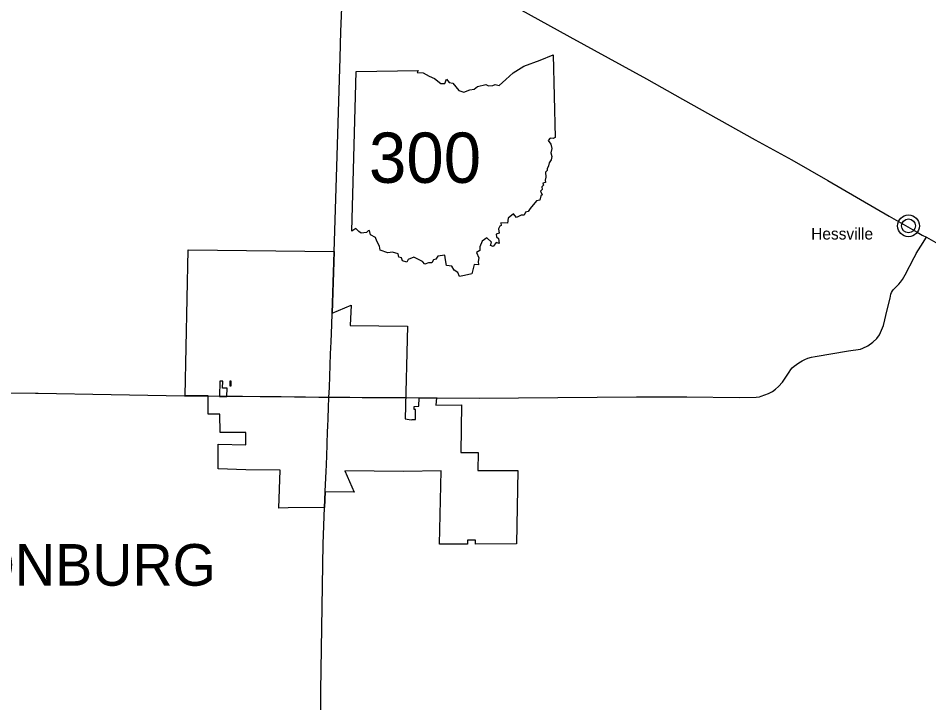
# Model space of a CAD drawing. Extents: x 0 to 798, y 0 to 440.
# Drawn here: x 204.7 to 286.7, y 218.5 to 280.2 of the extents above; entities that cross this region are included whole.
import ezdxf

# ---------------------------------------------------------------- set-up
doc = ezdxf.new("R2010")
doc.units = 0
for name, color, linetype in [('DV_X_Corp_Line', 7, 'Continuous'), ('GM_X_Corporation_Text', 7, 'Continuous'), ('GM_X_State_Route', 7, 'Continuous'), ('GM_X_US_Route', 7, 'Continuous'), ('PV_P_Text', 7, 'Continuous')]:
    doc.layers.add(name, color=color, linetype=linetype)

msp = doc.modelspace()

# ---------------------------------------------------------------- linework, layer by layer
at = {"layer": 'DV_X_Corp_Line'}
for points in [[(219.728, 246.15), (219.998, 259.294), (233.156, 259.134), (232.97, 253.586), (234.689, 254.313), (234.595, 252.489), (239.757, 252.419), (239.527, 244.072), (240.081, 243.994), (240.156, 244.005), (240.473, 244.016), (240.473, 244.919), (240.355, 244.915), (240.36, 245.19), (240.773, 245.205), (240.786, 245.983), (242.357, 245.974), (242.31, 245.31), (244.605, 245.35), (244.559, 241.044), (246.125, 241.04), (246.097, 239.439), (249.689, 239.424), (249.575, 232.818), (245.879, 232.806), (245.884, 233.144), (245.155, 233.144), (245.158, 232.795), (242.623, 232.78), (242.792, 239.381), (239.397, 239.345), (234.094, 239.401), (234.954, 237.463), (232.34, 237.513), (232.29, 236.107), (232.215, 236.105), (228.993, 236.049), (228.169, 236.035), (228.288, 239.462), (225.178, 239.495), (222.704, 239.578), (222.703, 241.784), (225.178, 241.728), (225.177, 242.849), (222.866, 242.849), (222.865, 244.5), (221.792, 244.499), (221.792, 246.15)], [(222.835, 246.103), (223.495, 246.103), (223.51, 246.832), (223.097, 246.841), (223.11, 247.466), (222.862, 247.471)], [(223.763, 247.466), (223.763, 247.036), (223.886, 247.036), (223.886, 247.466)]]:
    msp.add_lwpolyline(points, close=True, dxfattribs=at)
for radius in [0.982, 0.623]:
    msp.add_circle((284.866, 261.455), radius, dxfattribs=at)
at = {"layer": 'GM_X_State_Route'}
for points in [[(233.688, 276.598), (233.761, 278.953), (234.187, 289.718)], [(233.151, 259.127), (233.151, 259.127), (233.357, 265.82), (233.688, 276.598)], [(242.409, 245.974), (246.275, 245.95), (249.739, 245.974), (260.368, 246.047), (264.899, 246.045), (269.615, 246.01), (271.148, 246.023), (271.437, 246.057), (271.608, 246.111), (272.268, 246.35), (272.618, 246.552), (272.889, 246.744), (273.169, 246.993), (273.523, 247.391), (273.698, 247.653), (274.129, 248.295), (274.256, 248.525), (274.392, 248.66), (274.572, 248.82), (274.771, 248.976), (274.988, 249.125), (275.3, 249.304), (275.529, 249.417), (275.798, 249.528), (276.123, 249.629), (276.449, 249.704), (279.451, 250.21), (280.531, 250.366), (280.767, 250.436), (281.19, 250.639), (281.65, 250.994), (282.017, 251.314), (282.244, 251.634), (282.626, 252.497), (282.945, 253.887), (283.205, 254.948), (283.285, 255.318), (283.347, 255.467), (283.434, 255.602), (283.53, 255.721), (284.002, 256.196), (284.14, 256.375), (284.318, 256.624), (284.569, 257.037), (285.386, 258.607), (285.489, 258.816), (285.561, 258.97), (285.981, 259.627), (286.497, 260.433)], [(232.97, 253.586), (233.151, 259.127)], [(232.929, 252.544), (232.97, 253.586)], [(232.693, 246.423), (232.713, 246.941), (232.749, 247.881), (232.789, 248.92), (232.829, 249.943), (232.87, 251.006), (232.929, 252.535), (232.929, 252.544), (232.929, 252.544)], [(154.847, 246.999), (179.742, 246.677), (193.009, 246.54), (193.045, 246.503), (206.237, 246.386), (206.237, 246.386)], [(206.237, 246.386), (206.501, 246.383), (213.058, 246.26), (219.666, 246.156)], [(219.666, 246.156), (222.874, 246.131), (222.951, 246.131)], [(222.951, 246.131), (222.954, 246.131), (223.608, 246.125)], [(223.608, 246.125), (223.611, 246.125), (223.887, 246.123), (224.003, 246.122)], [(224.003, 246.122), (224.006, 246.122), (224.906, 246.115), (226.496, 246.103), (227.556, 246.094), (228.331, 246.085), (228.387, 246.084), (229.585, 246.07), (230.573, 246.058)], [(230.573, 246.058), (231.762, 246.043), (232.677, 246.032), (233.211, 246.029), (233.211, 246.029)], [(232.629, 244.985), (232.633, 245.067), (232.677, 246.032), (232.693, 246.423)], [(233.211, 246.029), (233.628, 246.026), (234.546, 246.021), (235.669, 246.014), (236.503, 246.009), (237.395, 246.004), (238.298, 245.998), (239.2, 245.993), (239.61, 245.99)], [(239.61, 245.99), (240.809, 245.983)], [(240.809, 245.983), (242.409, 245.974)], [(232.594, 244.199), (232.594, 244.209), (232.595, 244.239), (232.629, 244.985)], [(232.561, 243.021), (232.569, 243.306), (232.594, 244.199)], [(232.426, 239.354), (232.449, 239.911), (232.524, 241.693), (232.561, 243.018), (232.561, 243.021)], [(232.35, 237.522), (232.426, 239.351), (232.426, 239.354)], [(232.289, 236.082), (232.349, 237.519), (232.35, 237.522)], [(231.906, 206.373), (231.936, 219.585), (232.153, 232.809), (232.289, 236.082)]]:
    msp.add_lwpolyline(points, dxfattribs=at)
at = {"layer": 'GM_X_US_Route'}
for points in [[(248.019, 282.038), (254.368, 278.485), (261.264, 274.686), (264.516, 272.877), (271.054, 269.205), (274.346, 267.401), (277.607, 265.533), (283.14, 262.329), (283.955, 261.858), (284.816, 261.359), (285.651, 260.876), (285.787, 260.797)], [(285.787, 260.797), (286.094, 260.619), (286.497, 260.433)], [(286.497, 260.433), (287.526, 259.845)]]:
    msp.add_lwpolyline(points, dxfattribs=at)
at = {"layer": 'PV_P_Text'}
msp.add_line((234.737, 260.995), (235.139, 275.358), dxfattribs=at)
msp.add_line((234.737, 260.995), (235.139, 275.358), dxfattribs=at)
for points in [[(235.139, 275.358), (240.711, 275.451), (240.624, 275.278), (241.15, 275.241), (241.709, 274.934), (242.181, 274.741), (242.759, 274.284), (243.105, 274.289), (243.251, 274.664), (243.516, 274.375), (243.83, 274.323), (244.373, 273.636), (244.822, 273.487), (245.359, 273.722), (245.76, 273.761), (246.053, 273.994), (246.818, 274.193), (247.032, 274.074), (247.436, 274.098), (247.64, 274.186), (247.993, 274.107), (248.615, 274.629), (249.255, 275.245), (250.239, 275.826), (251.709, 276.377), (252.871, 276.869), (253.039, 269.415)], [(235.139, 275.358), (240.711, 275.451), (240.624, 275.278), (241.15, 275.241), (241.709, 274.934), (242.181, 274.741), (242.759, 274.284), (243.105, 274.289), (243.251, 274.664), (243.516, 274.375), (243.83, 274.323), (244.373, 273.636), (244.822, 273.487), (245.359, 273.722), (245.76, 273.761), (246.053, 273.994), (246.818, 274.193), (247.032, 274.074), (247.436, 274.098), (247.64, 274.186), (247.993, 274.107), (248.615, 274.629), (249.255, 275.245), (250.239, 275.826), (251.709, 276.377), (252.871, 276.869), (253.039, 269.415)], [(253.039, 269.415), (252.868, 269.311), (252.601, 269.36), (252.421, 269.151), (252.643, 268.802), (252.748, 268.434), (252.655, 268.028), (252.747, 267.693), (252.685, 267.412), (252.517, 267.133), (252.459, 266.867), (252.316, 266.587), (252.328, 266.43), (252.192, 266.306), (252.217, 265.84), (252.148, 265.581), (252.171, 265.359), (251.951, 265.3), (252.001, 265.116), (251.861, 264.974), (251.891, 264.729), (251.732, 264.573), (251.886, 264.26), (251.762, 264.161), (251.659, 263.781), (251.376, 263.704), (250.81, 263.008), (250.61, 262.745), (250.385, 262.68), (250.261, 262.41), (249.985, 262.408), (249.566, 262.221), (249.295, 262.544), (248.821, 262.156), (248.767, 261.708), (248.167, 261.722), (248.19, 261.496), (248.057, 261.43), (247.935, 261.203), (248.006, 260.8), (247.725, 260.697), (247.759, 260.463), (247.939, 260.32), (248.019, 259.873), (247.72, 259.963), (247.476, 259.587), (247.225, 259.675), (247.307, 259.994), (246.883, 260.378), (246.481, 260.071), (246.271, 259.579), (246.269, 259.249), (245.97, 259.049), (246.162, 258.582), (246.127, 258.26), (246.132, 257.955), (245.758, 257.965), (245.532, 257.141)], [(253.039, 269.415), (252.868, 269.311), (252.601, 269.36), (252.421, 269.151), (252.643, 268.802), (252.748, 268.434), (252.655, 268.028), (252.747, 267.693), (252.685, 267.412), (252.517, 267.133), (252.459, 266.867), (252.316, 266.587), (252.328, 266.43), (252.192, 266.306), (252.217, 265.84), (252.148, 265.581), (252.171, 265.359), (251.951, 265.3), (252.001, 265.116), (251.861, 264.974), (251.891, 264.729), (251.732, 264.573), (251.886, 264.26), (251.762, 264.161), (251.659, 263.781), (251.376, 263.704), (250.81, 263.008), (250.61, 262.745), (250.385, 262.68), (250.261, 262.41), (249.985, 262.408), (249.566, 262.221), (249.295, 262.544), (248.821, 262.156), (248.767, 261.708), (248.167, 261.722), (248.19, 261.496), (248.057, 261.43), (247.935, 261.203), (248.006, 260.8), (247.725, 260.697), (247.759, 260.463), (247.939, 260.32), (248.019, 259.873), (247.72, 259.963), (247.476, 259.587), (247.225, 259.675), (247.307, 259.994), (246.883, 260.378), (246.481, 260.071), (246.271, 259.579), (246.269, 259.249), (245.97, 259.049), (246.162, 258.582), (246.127, 258.26), (246.132, 257.955), (245.758, 257.965), (245.532, 257.141)], [(245.532, 257.141), (244.881, 256.983), (244.43, 256.889), (244.271, 257.263), (243.948, 257.461), (243.738, 257.838), (243.274, 257.889), (243.164, 258.407), (243.113, 258.827), (242.479, 258.724), (242.305, 258.467), (242.08, 258.398), (241.949, 258.139), (241.643, 258.117), (241.314, 257.995), (241.099, 258.249), (240.56, 258.504), (240.318, 258.636), (239.812, 258.431), (239.704, 258.189), (239.3, 258.296), (239.206, 258.566), (238.962, 258.647), (238.908, 258.933), (238.387, 259.085), (237.988, 259.025), (237.284, 259.255), (237.242, 259.631), (237.002, 260.09), (236.877, 260.408), (236.432, 260.651), (236.342, 261.03), (236.2, 261.019), (236.07, 260.865), (235.576, 260.795), (235.379, 260.949), (235.102, 261.213), (234.737, 260.995)], [(245.532, 257.141), (244.881, 256.983), (244.43, 256.889), (244.271, 257.263), (243.948, 257.461), (243.738, 257.838), (243.274, 257.889), (243.164, 258.407), (243.113, 258.827), (242.479, 258.724), (242.305, 258.467), (242.08, 258.398), (241.949, 258.139), (241.643, 258.117), (241.314, 257.995), (241.099, 258.249), (240.56, 258.504), (240.318, 258.636), (239.812, 258.431), (239.704, 258.189), (239.3, 258.296), (239.206, 258.566), (238.962, 258.647), (238.908, 258.933), (238.387, 259.085), (237.988, 259.025), (237.284, 259.255), (237.242, 259.631), (237.002, 260.09), (236.877, 260.408), (236.432, 260.651), (236.342, 261.03), (236.2, 261.019), (236.07, 260.865), (235.576, 260.795), (235.379, 260.949), (235.102, 261.213), (234.737, 260.995)]]:
    msp.add_lwpolyline(points, dxfattribs=at)

# ---------------------------------------------------------------- texts
at = {"layer": 'DV_X_Corp_Line'}
msp.add_text('Hessville', height=1.0417, rotation=0.00001, dxfattribs=at).set_placement((276.104, 260.228))
at = {"layer": 'GM_X_Corporation_Text'}
msp.add_text('GIBSONBURG', height=3.75, rotation=0.00001, dxfattribs=at).set_placement((188.51, 229.05))
at = {"layer": 'PV_P_Text'}
msp.add_text('300', height=4.5281, dxfattribs=at).set_placement((236.279, 265.333))

doc.saveas('drawing.dxf')
